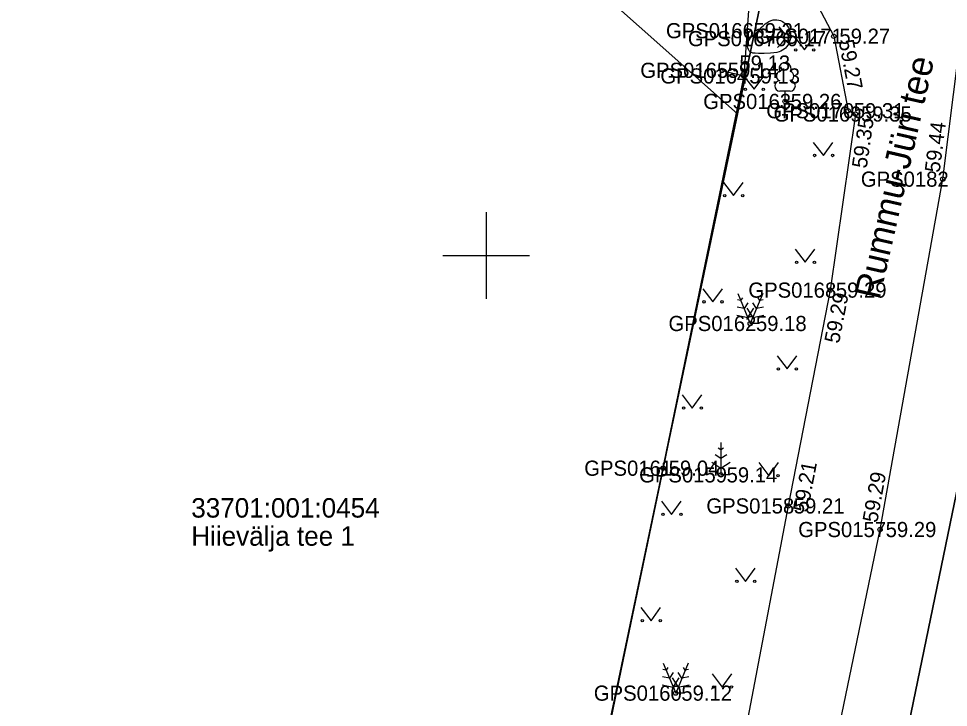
# Model space of a CAD drawing. Extents: x 551623 to 559850, y 6561220 to 6567135.
# Drawn here: x 556528.4 to 556571.35, y 6562529.14 to 6562560.95 of the extents above; entities that cross this region are included whole.
import ezdxf

# ---------------------------------------------------------------- set-up
doc = ezdxf.new("R2010")
doc.units = 0
for name, color, linetype in [('AED', 7, 'Continuous'), ('HALJASTUS', 7, 'Continuous'), ('KORGUS-EH2000', 7, 'Continuous'), ('MOOTKORG-EH2000', 7, 'Continuous'), ('MOOTMPUNKT', 7, 'Continuous'), ('MOOTNR', 7, 'Continuous'), ('MOOTPIIR', 7, 'Continuous'), ('PIIR', 7, 'Continuous'), ('PUU', 7, 'Continuous'), ('RELJEEF', 7, 'Continuous'), ('TEE', 7, 'Continuous'), ('VORK', 7, 'Continuous')]:
    doc.layers.add(name, color=color, linetype=linetype)

msp = doc.modelspace()

# ---------------------------------------------------------------- linework, layer by layer
at = {"layer": 'AED'}
msp.add_line((556560.894, 6562558.556), (556561.89, 6562558.297), dxfattribs=at)
msp.add_lwpolyline([(556561.89, 6562558.297), (556558.164, 6562540.182), (556554.238, 6562521.397), (556552.726, 6562513.925), (556552.161, 6562514.02)], dxfattribs=at)
at = {"layer": 'HALJASTUS'}
for p, q in [((556564.232, 6562560.104), (556564.696, 6562559.497)), ((556564.696, 6562559.497), (556565.141, 6562560.104)), ((556561.904, 6562558.289), (556562.367, 6562557.682)), ((556562.367, 6562557.682), (556562.813, 6562558.289)), ((556565.106, 6562555.231), (556565.569, 6562554.624)), ((556565.569, 6562554.624), (556566.015, 6562555.231)), ((556560.952, 6562553.38), (556561.416, 6562552.773)), ((556561.416, 6562552.773), (556561.861, 6562553.38)), ((556564.269, 6562550.301), (556564.733, 6562549.695)), ((556564.733, 6562549.695), (556565.178, 6562550.301)), ((556560.001, 6562548.471), (556560.464, 6562547.865)), ((556560.464, 6562547.865), (556560.91, 6562548.471)), ((556563.433, 6562545.372), (556563.896, 6562544.765)), ((556563.896, 6562544.765), (556564.342, 6562545.372)), ((556559.049, 6562543.563), (556559.512, 6562542.956)), ((556559.512, 6562542.956), (556559.958, 6562543.563)), ((556562.588, 6562540.444), (556563.051, 6562539.837)), ((556563.051, 6562539.837), (556563.497, 6562540.444)), ((556558.097, 6562538.654), (556558.561, 6562538.047)), ((556558.561, 6562538.047), (556559.006, 6562538.654)), ((556561.511, 6562535.561), (556561.975, 6562534.955)), ((556561.975, 6562534.955), (556562.42, 6562535.561)), ((556557.146, 6562533.746), (556557.609, 6562533.139)), ((556557.609, 6562533.139), (556558.055, 6562533.746)), ((556560.435, 6562530.678), (556560.898, 6562530.072)), ((556560.898, 6562530.072), (556561.344, 6562530.678))]:
    msp.add_line(p, q, dxfattribs=at)
for centre in [(556564.295, 6562559.497), (556565.124, 6562559.497), (556561.966, 6562557.682), (556562.795, 6562557.682), (556565.168, 6562554.624), (556565.997, 6562554.624), (556561.015, 6562552.773), (556561.844, 6562552.773), (556564.332, 6562549.695), (556565.16, 6562549.695), (556560.063, 6562547.865), (556560.892, 6562547.865), (556563.495, 6562544.765), (556564.324, 6562544.765), (556559.111, 6562542.956), (556559.94, 6562542.956), (556562.65, 6562539.837), (556563.479, 6562539.837), (556558.16, 6562538.047), (556558.989, 6562538.047), (556561.574, 6562534.955), (556562.402, 6562534.955), (556557.208, 6562533.139), (556558.037, 6562533.139), (556560.497, 6562530.072), (556561.326, 6562530.072)]:
    msp.add_circle(centre, 0.055, dxfattribs=at)
at = {"layer": 'KORGUS-EH2000'}
for centre in [(556566.051, 6562560.132), (556561.89, 6562558.297), (556567.051, 6562556.539), (556571.081, 6562553.531), (556565.885, 6562548.406), (556558.164, 6562540.182), (556563.944, 6562538.439), (556568.187, 6562537.349)]:
    msp.add_circle(centre, 0.1, dxfattribs=at)
at = {"layer": 'MOOTMPUNKT'}
for centre in [(556562.079, 6562560.387), (556566.051, 6562560.132), (556563.092, 6562560.021), (556560.894, 6562558.556), (556561.89, 6562558.297), (556563.801, 6562557.12), (556566.713, 6562556.691), (556567.051, 6562556.539), (556571.081, 6562553.531), (556565.885, 6562548.406), (556562.196, 6562546.865), (556558.164, 6562540.182), (556560.84, 6562539.873), (556563.944, 6562538.439), (556568.187, 6562537.349), (556558.748, 6562529.793)]:
    msp.add_circle(centre, 0.1, dxfattribs=at)
at = {"layer": 'MOOTPIIR'}
for points in [[(556618.715, 6562822.195), (556606.273, 6562747.18), (556599.844, 6562739.348), (556593.96, 6562711.51), (556588.43, 6562685.07), (556587.797, 6562685.099), (556586.503, 6562677.711), (556584.378, 6562665.61), (556582.242, 6562658.609), (556579.58, 6562644.209), (556576.324, 6562628.772), (556574.251, 6562619.959), (556568.733, 6562591.002), (556565.624, 6562580.56), (556564.07, 6562571.452), (556562.761, 6562565.324), (556562.362, 6562564.746), (556561.89, 6562558.297), (556552.726, 6562513.925), (556552.161, 6562514.02), (556543.863, 6562474.66)], [(556556.888, 6562482.698), (556561.272, 6562503.736), (556564.4, 6562519.072), (556568.187, 6562537.349), (556571.081, 6562553.531), (556572.069, 6562561.354), (556574.404, 6562572.858), (556576.101, 6562580.855), (556579.421, 6562594.083), (556583.237, 6562611.088), (556584.29, 6562616.041), (556587.083, 6562629.028), (556588.849, 6562637.213), (556592.933, 6562656.038), (556598.687, 6562681.695), (556602.285, 6562698.066), (556604.36, 6562708.434), (556605.991, 6562717.328), (556608.762, 6562730.722), (556610.742, 6562740.429), (556615.494, 6562765.342), (556618.725, 6562784.886)]]:
    msp.add_lwpolyline(points, dxfattribs=at)
at = {"layer": 'PIIR'}
for points in [[(556710.03, 6562313.25), (556617.42, 6562320.13), (556533.07, 6562326.41), (556527.9, 6562326.79), (556528.51, 6562329.75), (556582.07, 6562589.19), (556598.38, 6562665.28), (556613.6, 6562737.05), (556599.77, 6562739.31), (556564.04, 6562745.3), (556527.58, 6562751.46), (556484.67, 6562758.65), (556443.66, 6562765.51), (556431.83, 6562767.5), (556389.83, 6562774.53)], [(556455.22, 6562600.54), (556493.79, 6562589.57), (556529.82, 6562581.1), (556556.88, 6562576.51), (556566.59, 6562580.45), (556561.6, 6562556.55), (556554.72, 6562562.67), (556521.1, 6562568.54), (556481.19, 6562578.57), (556444.74, 6562588.67)]]:
    msp.add_lwpolyline(points, dxfattribs=at)
for points in [[(556599.77, 6562739.31), (556613.6, 6562737.05), (556598.38, 6562665.28), (556582.07, 6562589.19), (556528.51, 6562329.75), (556527.9, 6562326.79), (556533.07, 6562326.41), (556532.21, 6562322.88), (556529.17, 6562310.34), (556520.17, 6562273.55), (556523.22, 6562261.92), (556489.06, 6562281.04), (556502.86, 6562283.59), (556510.45, 6562310.26), (556519.14, 6562350.21), (556529.77, 6562402.46), (556539.62, 6562450.85), (556543.81, 6562471.43), (556552.64, 6562513.89), (556561.6, 6562556.55), (556566.59, 6562580.45), (556577.04, 6562630.35), (556588.43, 6562685.07), (556593.96, 6562711.51)], [(556561.6, 6562556.55), (556552.64, 6562513.89), (556511.16, 6562521.05), (556521.1, 6562568.54), (556554.72, 6562562.67)]]:
    msp.add_lwpolyline(points, close=True, dxfattribs=at)
at = {"layer": 'PUU'}
for p, q in [((556564.041, 6562557.595), (556563.561, 6562557.595)), ((556563.801, 6562557.12), (556563.801, 6562557.595)), ((556564.181, 6562557.12), (556563.801, 6562557.12)), ((556561.614, 6562548.248), (556562.196, 6562546.865)), ((556562.778, 6562548.248), (556562.196, 6562546.865)), ((556561.749, 6562547.925), (556561.603, 6562547.953)), ((556561.832, 6562548.05), (556561.749, 6562547.925)), ((556562.081, 6562547.824), (556561.905, 6562547.556)), ((556562.487, 6562547.556), (556562.31, 6562547.824)), ((556562.642, 6562547.925), (556562.56, 6562548.05)), ((556562.789, 6562547.953), (556562.642, 6562547.925)), ((556561.905, 6562547.556), (556561.59, 6562547.617)), ((556562.034, 6562547.573), (556562.315, 6562547.148)), ((556562.077, 6562547.148), (556562.358, 6562547.573)), ((556562.802, 6562547.617), (556562.487, 6562547.556)), ((556561.576, 6562547.244), (556562.077, 6562547.148)), ((556562.315, 6562547.148), (556562.816, 6562547.244)), ((556562.556, 6562546.865), (556562.196, 6562546.865)), ((556560.84, 6562541.373), (556560.84, 6562539.873)), ((556560.84, 6562541.023), (556560.715, 6562541.106)), ((556560.964, 6562541.106), (556560.84, 6562541.023)), ((556560.416, 6562540.463), (556560.84, 6562540.18)), ((556560.84, 6562540.623), (556560.573, 6562540.801)), ((556561.106, 6562540.801), (556560.84, 6562540.623)), ((556560.84, 6562540.18), (556561.264, 6562540.463)), ((556561.2, 6562539.873), (556560.84, 6562539.873)), ((556558.166, 6562531.175), (556558.748, 6562529.793)), ((556559.33, 6562531.175), (556558.748, 6562529.793)), ((556558.302, 6562530.853), (556558.155, 6562530.881)), ((556558.384, 6562530.978), (556558.302, 6562530.853)), ((556558.634, 6562530.751), (556558.457, 6562530.484)), ((556559.039, 6562530.484), (556558.862, 6562530.751)), ((556559.194, 6562530.853), (556559.112, 6562530.978)), ((556559.341, 6562530.881), (556559.194, 6562530.853)), ((556558.128, 6562530.171), (556558.629, 6562530.075)), ((556558.457, 6562530.484), (556558.142, 6562530.544)), ((556558.586, 6562530.501), (556558.867, 6562530.075)), ((556558.629, 6562530.075), (556558.91, 6562530.501)), ((556558.867, 6562530.075), (556559.368, 6562530.171)), ((556559.354, 6562530.544), (556559.039, 6562530.484)), ((556559.108, 6562529.793), (556558.748, 6562529.793))]:
    msp.add_line(p, q, dxfattribs=at)
for centre, radius, start, end in [((556563.631, 6562558.292), 0.233, 109.0217, 253.1415), ((556563.801, 6562558.64), 0.277, 332.5799, 207.4201), ((556563.971, 6562558.292), 0.233, 286.8508, 70.9859), ((556563.564, 6562557.832), 0.238, 90.0016, 269.3953), ((556564.038, 6562557.832), 0.238, 270.6047, 89.9984)]:
    msp.add_arc(centre, radius, start, end, dxfattribs=at)
at = {"layer": 'RELJEEF'}
for points in [[(556562.067, 6562559.736), (556562.086, 6562559.811), (556562.107, 6562559.876), (556562.129, 6562559.93), (556562.16, 6562559.987), (556562.211, 6562560.057), (556562.273, 6562560.12), (556562.359, 6562560.197), (556562.496, 6562560.322), (556562.586, 6562560.412), (556562.714, 6562560.544), (556562.786, 6562560.615), (556562.883, 6562560.699), (556562.958, 6562560.754), (556563.047, 6562560.808), (556563.156, 6562560.858), (556563.245, 6562560.885), (556563.341, 6562560.896), (556563.424, 6562560.893), (556563.511, 6562560.877), (556563.588, 6562560.852), (556563.688, 6562560.805), (556563.749, 6562560.766), (556563.832, 6562560.698), (556563.888, 6562560.638), (556563.945, 6562560.556), (556563.979, 6562560.493), (556564.011, 6562560.412), (556564.033, 6562560.329), (556564.046, 6562560.247), (556564.051, 6562560.163), (556564.047, 6562560.071), (556564.033, 6562559.976), (556564.009, 6562559.886), (556563.97, 6562559.792), (556563.927, 6562559.718), (556563.874, 6562559.645), (556563.814, 6562559.58), (556563.759, 6562559.532), (556563.685, 6562559.482), (556563.6, 6562559.439), (556563.526, 6562559.411), (556563.423, 6562559.386), (556563.288, 6562559.365), (556563.131, 6562559.351), (556562.833, 6562559.338), (556562.57, 6562559.337), (556562.414, 6562559.343), (556562.319, 6562559.356), (556562.246, 6562559.378), (556562.187, 6562559.41), (556562.139, 6562559.456), (556562.106, 6562559.512), (556562.083, 6562559.589), (556562.072, 6562559.664), (556562.067, 6562559.736)], [(556563.452, 6562559.606), (556563.494, 6562559.651), (556563.563, 6562559.724), (556563.631, 6562559.798), (556563.698, 6562559.871), (556563.755, 6562559.953), (556563.78, 6562560.05), (556563.78, 6562560.149), (556563.759, 6562560.247), (556563.717, 6562560.337), (556563.654, 6562560.415), (556563.588, 6562560.49), (556563.522, 6562560.565)]]:
    msp.add_lwpolyline(points, dxfattribs=at)
at = {"layer": 'TEE'}
for points in [[(556556.888, 6562482.698), (556561.272, 6562503.736), (556564.4, 6562519.072), (556568.187, 6562537.349), (556571.081, 6562553.531), (556572.069, 6562561.354), (556574.404, 6562572.858), (556576.101, 6562580.855), (556579.421, 6562594.083), (556583.237, 6562611.088), (556584.29, 6562616.041), (556587.083, 6562629.028), (556588.849, 6562637.213), (556592.933, 6562656.038), (556598.687, 6562681.695), (556602.285, 6562698.066), (556604.36, 6562708.434), (556605.991, 6562717.328), (556608.762, 6562730.722), (556610.742, 6562740.429)], [(556562.761, 6562565.324), (556564.707, 6562563.562), (556564.57, 6562562.955), (556566.051, 6562560.132), (556566.713, 6562556.691), (556567.051, 6562556.539), (556565.885, 6562548.406), (556563.944, 6562538.439), (556560.47, 6562520.162), (556557.327, 6562504.664), (556552.899, 6562483.554), (556548.475, 6562463.847), (556546.711, 6562456.111), (556542.048, 6562433.596), (556535.231, 6562402.146), (556530.556, 6562380.69), (556526.024, 6562360.541), (556521.674, 6562342.907), (556517.076, 6562323.398), (556516.506, 6562321.348), (556514.845, 6562321.726), (556512.019, 6562322.67)]]:
    msp.add_lwpolyline(points, dxfattribs=at)
at = {"layer": 'VORK'}
for p, q in [((556550, 6562552), (556550, 6562548)), ((556548, 6562550), (556552, 6562550))]:
    msp.add_line(p, q, dxfattribs=at)

# ---------------------------------------------------------------- texts
at = {"layer": 'KORGUS-EH2000'}
for s, rotation, p in [(' 59.27', 280.8911, (556566.223, 6562560.165)), (' 59.35', 81.843, (556567.535, 6562553.747)), (' 59.44', 82.7992, (556570.907, 6562553.552)), (' 59.29', 78.9814, (556566.244, 6562545.657)), (' 59.21', 79.2358, (556564.793, 6562537.863)), (' 59.29', 79.8607, (556568.014, 6562537.379))]:
    msp.add_text(s, height=0.7, rotation=rotation, dxfattribs=at).set_placement(p)
for s, p in [(' 59.13', (556561.432, 6562558.543)), (' 59.04', (556558.164, 6562539.832))]:
    msp.add_text(s, height=0.7, dxfattribs=at).set_placement(p)
at = {"layer": 'MOOTKORG-EH2000'}
for s, p in [(' 59.21', (556562.079, 6562560.037)), (' 60.17', (556563.092, 6562559.671)), (' 59.27', (556566.051, 6562559.782)), (' 59.14', (556560.894, 6562558.206)), (' 59.13', (556561.89, 6562557.947)), (' 59.26', (556563.801, 6562556.77)), (' 59.31', (556566.713, 6562556.341)), (' 59.35', (556567.051, 6562556.189)), (' 59.29', (556565.885, 6562548.056)), (' 59.18', (556562.196, 6562546.515)), (' 59.04', (556558.164, 6562539.832)), (' 59.14', (556560.84, 6562539.523)), (' 59.21', (556563.944, 6562538.089)), (' 59.29', (556568.187, 6562536.999)), (' 59.12', (556558.748, 6562529.443))]:
    msp.add_text(s, height=0.7, dxfattribs=at).set_placement(p)
at = {"layer": 'MOOTNR'}
for s, p in [('GPS0166 ', (556558.3, 6562560.037)), ('GPS0167 ', (556559.312, 6562559.671)), ('GPS0171 ', (556562.411, 6562559.782)), ('GPS0165 ', (556557.114, 6562558.206)), ('GPS0164 ', (556558.04, 6562557.947)), ('GPS0163 ', (556560.021, 6562556.77)), ('GPS0170 ', (556562.933, 6562556.341)), ('GPS0169 ', (556563.271, 6562556.189)), ('GPS0182 ', (556567.301, 6562553.181)), ('GPS0168 ', (556562.105, 6562548.056)), ('GPS0162 ', (556558.416, 6562546.515)), ('GPS0161 ', (556554.525, 6562539.832)), ('GPS0159 ', (556557.06, 6562539.523)), ('GPS0158 ', (556560.165, 6562538.089)), ('GPS0157 ', (556564.407, 6562536.999)), ('GPS0160 ', (556554.968, 6562529.443))]:
    msp.add_text(s, height=0.7, dxfattribs=at).set_placement(p)
at = {"layer": 'PIIR'}
for s, p in [('33701:001:0454', (556536.374, 6562537.9)), ('Hiievälja tee 1', (556536.374, 6562536.6))]:
    msp.add_text(s, height=0.9, dxfattribs=at).set_placement(p)
at = {"layer": 'TEE'}
msp.add_text('Rummu-Jüri tee', height=1.2, rotation=77.1448, dxfattribs=at).set_placement((556568.16, 6562547.929))

doc.saveas('drawing.dxf')
